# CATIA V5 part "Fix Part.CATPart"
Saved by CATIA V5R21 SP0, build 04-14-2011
Part number: Part4
Bounding box of the stored display mesh (mm): x -100 to 100, y -60 to 60, z -30 to 80.884
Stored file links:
  D:\CATIA V5R21 E-RESOURCES\CATIA-V5R21\catia-v5r21-Prts\c16_catia_v5r21_prt\Rack Joint(Fig16-57)\Fix Part.CATPart
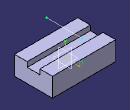
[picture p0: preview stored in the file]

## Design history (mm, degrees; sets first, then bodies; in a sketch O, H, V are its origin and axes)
Body1 (main body)
  Sketch1 on yz-plane, origin (0, 0, 0), H (0, 1, 0), V (0, 0, 1)
    line L1 (60, 30) -> (60, -30)
    line L2 (60, -30) -> (-60, -30)
    line L3 (-60, -30) -> (-60, 30)
    point P1 (60, 30)
    point P4 (-60, 30)
    point P5 (20, 30)
    line L4 (-20, 30) -> (-20, 14.3569)
    line L5 (-20, 14.3569) -> (20, 14.3569)
    line L6 (20, 14.3569) -> (20, 30)
    point P6 (-20, 30)
    point P7 (-20, 14.3569)
    point P8 (20, 14.3569)
    reference intersected line E1 through (0, 0) direction (-1, 0) from xy-plane
    reference intersected line E3 through (0, 0) direction (0, 1) from zx-plane
    line L7 (20, 30) -> (60, 30)
    line L8 (-20, 30) -> (-60, 30)
    reference intersected line E4 through (0, 0) direction (-1, 0) from xy-plane
    reference intersected line E6 through (0, 0) direction (0, 1) from zx-plane
    distance H L2 = 30
    distance V L1 = 60
    distance E1 L5 = 14.3569
    distance L4 L6 = 40
    distance P7 E3 = 20
    distance P5 P8 = 15.6431
    vertical: L1 V, L3 V, L4 V, L6 V, E3 V, E6 V
    horizontal: L2 H, L5 H, E1 H, L7 H, L8 H, E4 H
    equidistance: L1 L3 O
    perpendicularity: E1 L1
    coincidence: P1 L8, P4 L7, P5 L8, P6 L7, L7 L8
  Pad1: profile Sketch1, direction (1, 0, 0), length 100, mirrored extent
  Sketch2 on yz-plane, origin (0, 0, 0), H (0, 1, 0), V (0, 0, 1)
    line L1 (52.4742, 80.8837) -> (-58.5645, 80.8837)
    point P1 (52.4742, 80.8837)
    point P2 (-58.5645, 80.8837)
    distance P1 P2 = 111.0387
    horizontal: L1 H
